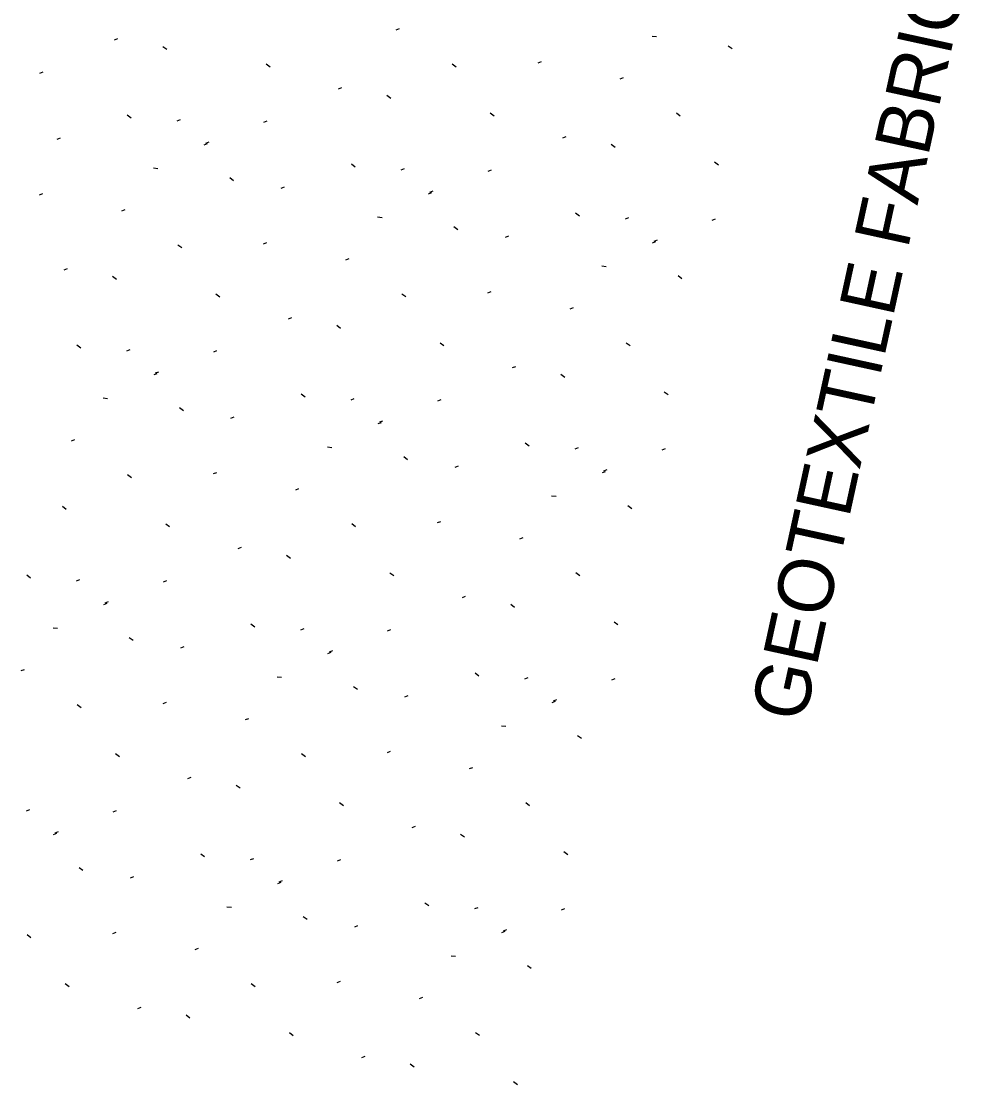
# Model space of a CAD drawing. Extents: x 2126110 to 2128246, y 1804858 to 1811658.
# Drawn here: x 2126619.8 to 2126704.9, y 1805332.2 to 1805428.3 of the extents above; entities that cross this region are included whole.
import ezdxf

# ---------------------------------------------------------------- set-up
doc = ezdxf.new("R2010")
doc.units = 0
doc.layers.add('1', color=7, linetype='Continuous')

msp = doc.modelspace()

# ---------------------------------------------------------------- linework, layer by layer
at = {"layer": '1'}
for p, q in [((2126653.648, 1805427.562), (2126653.947, 1805427.679)), ((2126628.188, 1805426.67), (2126628.487, 1805426.786)), ((2126676.78, 1805427.007), (2126677.179, 1805426.965)), ((2126632.911, 1805425.787), (2126632.559, 1805426.046)), ((2126684.025, 1805425.844), (2126683.672, 1805426.102)), ((2126642.251, 1805424.201), (2126641.898, 1805424.46)), ((2126659.068, 1805424.207), (2126658.716, 1805424.466)), ((2126666.474, 1805424.589), (2126666.773, 1805424.705)), ((2126621.434, 1805423.662), (2126621.732, 1805423.779)), ((2126673.911, 1805423.134), (2126674.209, 1805423.251)), ((2126648.451, 1805422.242), (2126648.749, 1805422.359)), ((2126653.174, 1805421.359), (2126652.821, 1805421.618)), ((2126629.692, 1805419.582), (2126629.34, 1805419.841)), ((2126662.513, 1805419.773), (2126662.161, 1805420.032)), ((2126679.331, 1805419.779), (2126678.978, 1805420.038)), ((2126633.848, 1805419.336), (2126634.147, 1805419.452)), ((2126641.697, 1805419.235), (2126641.995, 1805419.351)), ((2126622.998, 1805417.689), (2126623.297, 1805417.806)), ((2126668.714, 1805417.814), (2126669.012, 1805417.931)), ((2126636.303, 1805417.183), (2126636.601, 1805417.3)), ((2126636.44, 1805417.335), (2126636.738, 1805417.452)), ((2126673.436, 1805416.932), (2126673.084, 1805417.19)), ((2126631.714, 1805415.084), (2126632.114, 1805415.042)), ((2126649.955, 1805415.155), (2126649.602, 1805415.414)), ((2126654.111, 1805414.908), (2126654.409, 1805415.025)), ((2126661.959, 1805414.807), (2126662.258, 1805414.924)), ((2126682.776, 1805415.345), (2126682.423, 1805415.604)), ((2126638.959, 1805413.921), (2126638.607, 1805414.18)), ((2126643.261, 1805413.262), (2126643.559, 1805413.378)), ((2126656.702, 1805412.907), (2126657.001, 1805413.024)), ((2126621.409, 1805412.666), (2126621.707, 1805412.782)), ((2126656.566, 1805412.755), (2126656.864, 1805412.872)), ((2126628.845, 1805411.211), (2126629.144, 1805411.328)), ((2126670.217, 1805410.727), (2126669.865, 1805410.986)), ((2126651.977, 1805410.656), (2126652.376, 1805410.614)), ((2126674.374, 1805410.48), (2126674.672, 1805410.597)), ((2126682.222, 1805410.379), (2126682.52, 1805410.496)), ((2126659.222, 1805409.493), (2126658.869, 1805409.752)), ((2126634.265, 1805407.857), (2126633.913, 1805408.115)), ((2126641.671, 1805408.238), (2126641.97, 1805408.354)), ((2126663.523, 1805408.834), (2126663.822, 1805408.951)), ((2126676.828, 1805408.327), (2126677.126, 1805408.444)), ((2126676.965, 1805408.479), (2126677.263, 1805408.596)), ((2126649.108, 1805406.784), (2126649.406, 1805406.9)), ((2126672.239, 1805406.228), (2126672.639, 1805406.186)), ((2126623.648, 1805405.891), (2126623.946, 1805406.008)), ((2126628.371, 1805405.009), (2126628.018, 1805405.268)), ((2126679.484, 1805405.065), (2126679.132, 1805405.324)), ((2126637.71, 1805403.422), (2126637.358, 1805403.681)), ((2126654.528, 1805403.429), (2126654.175, 1805403.688)), ((2126661.934, 1805403.81), (2126662.232, 1805403.927)), ((2126669.37, 1805402.356), (2126669.669, 1805402.472)), ((2126643.91, 1805401.464), (2126644.209, 1805401.58)), ((2126648.633, 1805400.581), (2126648.281, 1805400.84)), ((2126625.152, 1805398.804), (2126624.799, 1805399.063)), ((2126629.308, 1805398.557), (2126629.606, 1805398.674)), ((2126637.156, 1805398.456), (2126637.455, 1805398.573)), ((2126657.973, 1805398.995), (2126657.62, 1805399.253)), ((2126674.79, 1805399.001), (2126674.438, 1805399.26)), ((2126631.899, 1805396.556), (2126632.198, 1805396.673)), ((2126664.173, 1805397.036), (2126664.471, 1805397.152)), ((2126631.763, 1805396.405), (2126632.061, 1805396.521)), ((2126668.896, 1805396.153), (2126668.544, 1805396.412)), ((2126645.414, 1805394.376), (2126645.062, 1805394.635)), ((2126678.235, 1805394.567), (2126677.883, 1805394.826)), ((2126627.174, 1805394.305), (2126627.573, 1805394.263)), ((2126649.571, 1805394.13), (2126649.869, 1805394.246)), ((2126657.419, 1805394.029), (2126657.717, 1805394.145)), ((2126634.419, 1805393.142), (2126634.066, 1805393.401)), ((2126638.72, 1805392.483), (2126639.019, 1805392.6)), ((2126652.025, 1805391.977), (2126652.323, 1805392.093)), ((2126652.162, 1805392.129), (2126652.46, 1805392.245)), ((2126624.305, 1805390.433), (2126624.603, 1805390.549)), ((2126647.436, 1805389.877), (2126647.836, 1805389.836)), ((2126665.677, 1805389.949), (2126665.324, 1805390.207)), ((2126654.681, 1805388.715), (2126654.329, 1805388.973)), ((2126669.833, 1805389.702), (2126670.131, 1805389.818)), ((2126677.681, 1805389.601), (2126677.98, 1805389.717)), ((2126658.983, 1805388.056), (2126659.281, 1805388.172)), ((2126629.725, 1805387.078), (2126629.372, 1805387.337)), ((2126637.131, 1805387.459), (2126637.429, 1805387.576)), ((2126672.288, 1805387.549), (2126672.586, 1805387.666)), ((2126672.425, 1805387.701), (2126672.723, 1805387.818)), ((2126644.567, 1805386.005), (2126644.866, 1805386.122)), ((2126667.699, 1805385.45), (2126668.098, 1805385.408)), ((2126623.83, 1805384.23), (2126623.478, 1805384.489)), ((2126674.944, 1805384.287), (2126674.591, 1805384.546)), ((2126657.393, 1805383.032), (2126657.692, 1805383.148)), ((2126633.17, 1805382.644), (2126632.817, 1805382.903)), ((2126649.987, 1805382.65), (2126649.635, 1805382.909)), ((2126664.83, 1805381.577), (2126665.128, 1805381.694)), ((2126639.37, 1805380.685), (2126639.668, 1805380.802)), ((2126644.093, 1805379.803), (2126643.74, 1805380.061)), ((2126653.432, 1805378.216), (2126653.08, 1805378.475)), ((2126670.25, 1805378.223), (2126669.897, 1805378.481)), ((2126620.611, 1805378.026), (2126620.259, 1805378.284)), ((2126624.767, 1805377.779), (2126625.066, 1805377.896)), ((2126632.616, 1805377.678), (2126632.914, 1805377.794)), ((2126659.633, 1805376.257), (2126659.931, 1805376.374)), ((2126627.222, 1805375.626), (2126627.52, 1805375.743)), ((2126627.359, 1805375.778), (2126627.657, 1805375.895)), ((2126664.356, 1805375.375), (2126664.003, 1805375.634)), ((2126622.633, 1805373.527), (2126623.033, 1805373.485)), ((2126640.874, 1805373.598), (2126640.521, 1805373.857)), ((2126673.695, 1805373.788), (2126673.343, 1805374.047)), ((2126629.878, 1805372.364), (2126629.526, 1805372.623)), ((2126645.03, 1805373.351), (2126645.328, 1805373.468)), ((2126652.878, 1805373.25), (2126653.177, 1805373.367)), ((2126634.18, 1805371.705), (2126634.478, 1805371.822)), ((2126647.485, 1805371.198), (2126647.783, 1805371.315)), ((2126647.622, 1805371.35), (2126647.92, 1805371.467)), ((2126619.764, 1805369.654), (2126620.063, 1805369.771)), ((2126642.896, 1805369.099), (2126643.295, 1805369.057)), ((2126661.136, 1805369.17), (2126660.784, 1805369.429)), ((2126665.293, 1805368.923), (2126665.591, 1805369.04)), ((2126673.141, 1805368.822), (2126673.439, 1805368.939)), ((2126650.141, 1805367.936), (2126649.788, 1805368.195)), ((2126632.59, 1805366.681), (2126632.889, 1805366.798)), ((2126654.442, 1805367.277), (2126654.741, 1805367.394)), ((2126667.747, 1805366.771), (2126668.046, 1805366.887)), ((2126667.884, 1805366.923), (2126668.182, 1805367.039)), ((2126625.184, 1805366.3), (2126624.832, 1805366.559)), ((2126640.027, 1805365.227), (2126640.325, 1805365.343)), ((2126663.158, 1805364.671), (2126663.558, 1805364.63)), ((2126670.403, 1805363.508), (2126670.051, 1805363.767)), ((2126628.629, 1805361.866), (2126628.277, 1805362.124)), ((2126645.447, 1805361.872), (2126645.094, 1805362.131)), ((2126652.853, 1805362.253), (2126653.151, 1805362.37)), ((2126660.29, 1805360.799), (2126660.588, 1805360.916)), ((2126634.83, 1805359.907), (2126635.128, 1805360.023)), ((2126639.553, 1805359.024), (2126639.2, 1805359.283)), ((2126648.892, 1805357.438), (2126648.54, 1805357.697)), ((2126665.709, 1805357.444), (2126665.357, 1805357.703)), ((2126620.227, 1805357), (2126620.525, 1805357.117)), ((2126628.075, 1805356.899), (2126628.374, 1805357.016)), ((2126655.092, 1805355.479), (2126655.39, 1805355.596)), ((2126622.682, 1805354.848), (2126622.98, 1805354.964)), ((2126622.818, 1805355), (2126623.117, 1805355.116)), ((2126659.815, 1805354.596), (2126659.463, 1805354.855)), ((2126636.333, 1805352.82), (2126635.981, 1805353.078)), ((2126640.49, 1805352.573), (2126640.788, 1805352.689)), ((2126648.338, 1805352.472), (2126648.636, 1805352.588)), ((2126669.155, 1805353.01), (2126668.802, 1805353.269)), ((2126625.338, 1805351.585), (2126624.985, 1805351.844)), ((2126629.639, 1805350.926), (2126629.938, 1805351.043)), ((2126642.944, 1805350.42), (2126643.243, 1805350.537)), ((2126643.081, 1805350.572), (2126643.379, 1805350.689)), ((2126656.596, 1805348.392), (2126656.243, 1805348.651)), ((2126638.355, 1805348.321), (2126638.755, 1805348.279)), ((2126660.752, 1805348.145), (2126661.05, 1805348.262)), ((2126668.601, 1805348.044), (2126668.899, 1805348.161)), ((2126645.6, 1805347.158), (2126645.248, 1805347.417)), ((2126649.902, 1805346.499), (2126650.2, 1805346.615)), ((2126620.644, 1805345.521), (2126620.291, 1805345.78)), ((2126628.05, 1805345.903), (2126628.348, 1805346.019)), ((2126663.207, 1805345.992), (2126663.505, 1805346.109)), ((2126663.344, 1805346.144), (2126663.642, 1805346.261)), ((2126635.486, 1805344.448), (2126635.785, 1805344.565)), ((2126658.618, 1805343.893), (2126659.018, 1805343.851)), ((2126665.863, 1805342.73), (2126665.51, 1805342.989)), ((2126624.089, 1805341.087), (2126623.736, 1805341.346)), ((2126640.906, 1805341.094), (2126640.554, 1805341.352)), ((2126648.312, 1805341.475), (2126648.611, 1805341.592)), ((2126655.749, 1805340.021), (2126656.047, 1805340.137)), ((2126630.289, 1805339.128), (2126630.587, 1805339.245)), ((2126635.012, 1805338.246), (2126634.66, 1805338.505)), ((2126644.352, 1805336.659), (2126643.999, 1805336.918)), ((2126661.169, 1805336.666), (2126660.816, 1805336.925)), ((2126650.552, 1805334.701), (2126650.85, 1805334.817)), ((2126655.275, 1805333.818), (2126654.922, 1805334.077)), ((2126664.614, 1805332.232), (2126664.262, 1805332.49))]:
    msp.add_line(p, q, dxfattribs=at)

# ---------------------------------------------------------------- texts
msp.add_text('GEOTEXTILE FABRIC', height=4.99999, rotation=77.67359, dxfattribs=at).set_placement((2126690.532, 1805364.839))

doc.saveas('drawing.dxf')
